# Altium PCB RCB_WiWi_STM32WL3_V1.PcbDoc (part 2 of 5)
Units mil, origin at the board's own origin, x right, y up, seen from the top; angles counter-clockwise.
Board outline 1250.1 x 2647.64 mil, 10 copper layers (L01-TOP, L02-GND, L03-SIG, L04-GND, L05-PWR, L06-PWR, L07-GND, L08-SIG, L09-GND, L10-BOT), stack 62.1 mil thick; 342 components, 203 nets, 969 pads, 708 vias.
Unrouted connection lines stored in the file: 108.
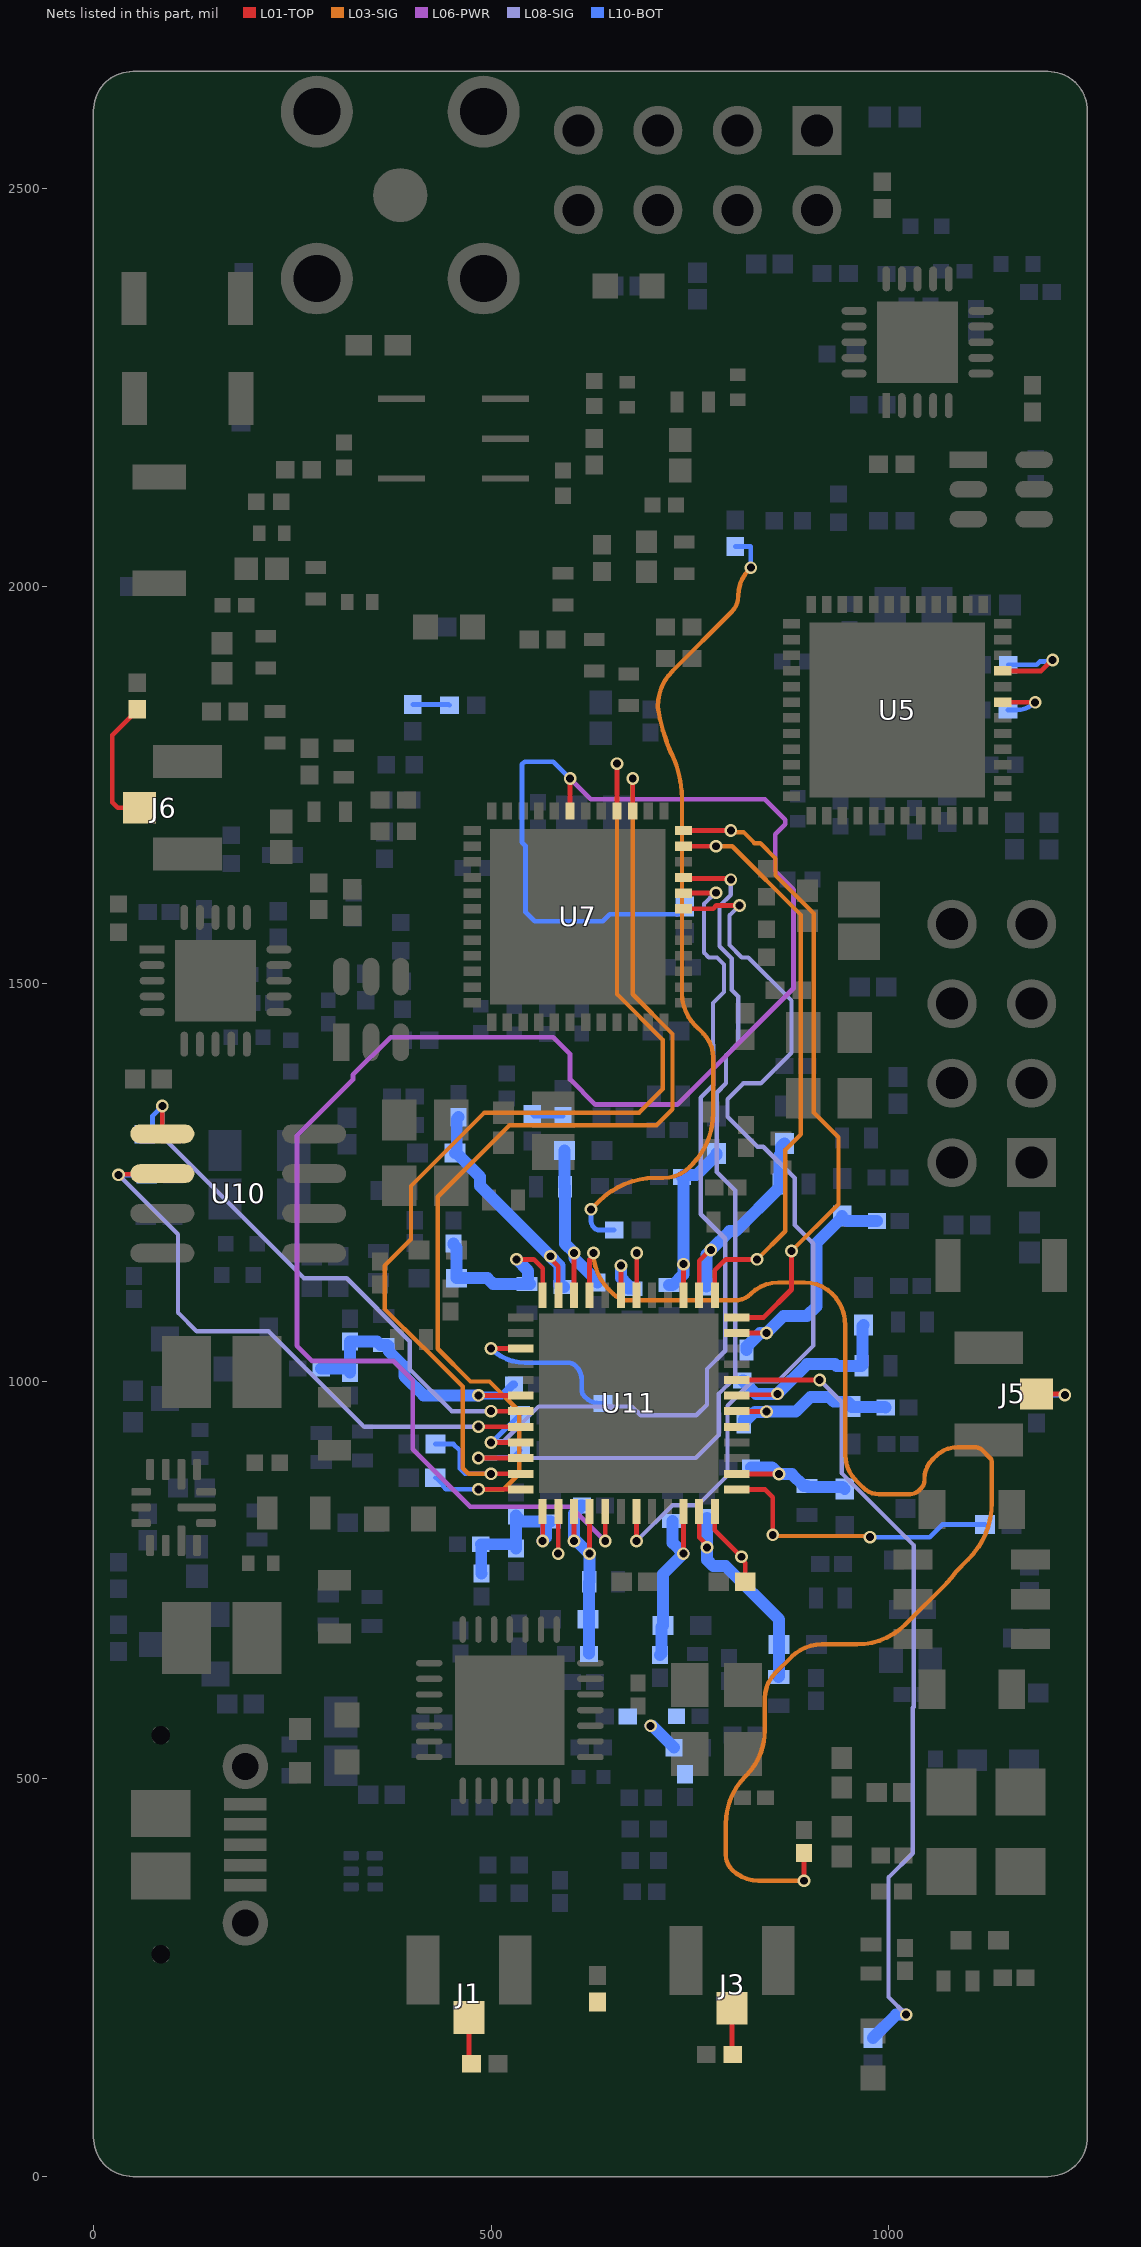
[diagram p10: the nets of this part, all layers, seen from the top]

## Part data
C1 C22 C24 C40 C41 C42 C44 C58 C62 C64 C68 C71 C73 C77 C80 C84 C87 C90 C92 C94 C97 C100 C102 C104 C107 C109 C112 C114 C131 C133 C147 C149: library part CMP-13271-000002-1, "CAP CER 10UF 10V X5R 0402", Capacitance=10uF, Manufacturer=Samsung, Manufacturer Part Number=CL05A106MP5NUNC, Temperature="-55°C to +85°C", Temperature Characteristic=X5R, Temperature Coefficient=15%, Temperature Range High=+85°C, Temperature Range Low=-55°C, Tolerance=20%, Voltage Rating=10V
C2 C13 C21 C23 C25 C26 C27 C31 C32 C33 C34 C47 C51 C55 C59 C60 C63 C65 C66 C67 C69 C70 C72 C74 C75 C76 C78 C79 C81 C82 C83 C85 C86 C88 C89 C91 C93 C95 C96 C98 C99 C101 C103 C106 C108 C110 C111 C113 C115 C118 C119 C121 C126 C127 C132 C134 C148 C150: library part CMP-2008-02519-2, "General Purpose Ceramic Capacitor, 0402, 100nF, 10%, X7R, 15%, 25V", Capacitance=100nF, Case Code (Imperial)=0402, Case Code (Metric)=1005, Dielectric=X7R, Max Operating Temperature=125°C, Min Operating Temperature=-55°C, Package Quantity=1, Tolerance=10%, Voltage=25V
C3 C8 C14 C19: library part CMP-2008-03915-1, Manufacturer=Murata, Part Number=GRM1555C1H101JA01D
C4 C15: library part CMP-2008-03815-2, "Multi-Layer Ceramic Capacitor 1.2pF C0G  ±0.05pF 0402 Paper T/R", Capacitance=1.2pF, Case Code (Imperial)=0402, Case Code (Metric)=1005, Dielectric=C0G, Max Operating Temperature=125°C, Min Operating Temperature=-55°C, Package Quantity=10000, Voltage=50V
C5 C6 C16 C17: library part CMP-06035-005630-1, "Multi-Layer Ceramic Capacitor 5pF C0G  ±0.05pF 0402 Paper T/R", Capacitance=5pF, Case Code (Imperial)=0402, Case Code (Metric)=1005, Dielectric=C0G, Max Operating Temperature=125°C, Min Operating Temperature=-55°C, Package Quantity=10000, Voltage Rating=50V
C7 C18: library part CMP-2008-03837-2, "Multi-Layer Ceramic Capacitor 2.2pF C0G  ±0.05pF 0402 Paper T/R", Capacitance=2.2pF, Case Code (Imperial)=0402, Case Code (Metric)=1005, Dielectric=C0G, Max Operating Temperature=125°C, Min Operating Temperature=-55°C, Package Quantity=10000, Voltage Rating=50V
C9 C10 C20 C28: library part CMP-2008-03904-2, "Multi-Layer Ceramic Capacitor 0.5pF C0G  ±0.1pF 0402 Paper T/R", Capacitance=0.5pF, Case Code (Imperial)=0402, Case Code (Metric)=1005, Dielectric=C0G, Max Operating Temperature=125°C, Min Operating Temperature=-55°C, Package Quantity=1, Temperature Coefficient=30ppm/°C, Voltage=50V
C11 C12 C29 C30 C35 C135 C137 C138 C139 C143 C151 C153 C154 C155 C159: library part CMP-1034-02068-3, "CAP CER 0.1UF 16V 5% X7R 0402", Capacitance="0.10 μF", Manufacturer=Kemet, Manufacturer Part Number=C0402C104J4RACTU, Package=C0402-BB, Temperature="-55°C to +125°C", Temperature Characteristic=X7R, Temperature Coefficient=15%, Temperature Range High=+125°C, Temperature Range Low=-55°C, Tolerance=0.05, Voltage Rating="16 V"
C36 C37 C140 C142 C156 C158: library part CMP-2000-05997-2, "CAP CER 4.7UF 10V X5R 0402", Capacitance=4.7uF, Case Code (Imperial)=0402, Case Code (Metric)=1005, Dielectric=X5R, Dielectric Material=Ceramic, Max Operating Temperature=85°C, Min Operating Temperature=-55°C, Package Quantity=10000, Tolerance=10%, Voltage Rating=10V
C38 C45 C48: library part CMP-2000-05441-1, "Chip Capacitor, 22 uF, +/- 20%, 10 V, -55 to 85 degC, 0603 (1608 Metric), RoHS, Tape and Reel", Capacitance=22µF, Manufacturer=TDK, Operating Temperature=-55degC~85degC, Package / Case=0603(1608Metric), Package Description="2-Pin Surface Mount Device, Body 1.6 x 0.8 mm", Package Reference=603, PCN Part Number=MLCCPartNumberChange30/Nov/2012, Ratings=-, Standard Package=1, Temperature Coefficient=X5R, Tolerance=±20%, Voltage - Rated=10V
C39 C43: library part CMP-08246-002674-1, "CAP CER 10PF 50V C0G 0402", Capacitance=10pF, Case Code (Imperial)=0402, Case Code (Metric)=1005, Dielectric=C0G, Dielectric Material=Ceramic, Max Operating Temperature=125°C, Min Operating Temperature=-55°C, Package Quantity=1, Temperature Coefficient=30ppm/°C, Voltage=50V
C46 C50 C117 C120 C125: library part CMP-2100-03592-2, "CAP CER 10000PF 50V X7R 0402", Capacitance="10 nF", Manufacturer=YAGEO, Manufacturer Part Number=CC0402KRX7R9BB103, Package=CC0402, Temperature="-55°C to +125°C", Temperature Characteristic=X7R, Temperature Coefficient=30ppm/°C, Temperature Range High=+125°C, Temperature Range Low=-55°C, Tolerance=0.1, Voltage Rating="50 V"
C49 C52 C122: library part CMP-13271-001468-1, "Cap Ceramic 4.7uF 16V X5R ±20% SMD 0402 +85°C Paper T/R", Capacitance=4.7uF, Case Code (Imperial)=0402, Case Code (Metric)=1005, Max Operating Temperature=85°C, Min Operating Temperature=-55°C, Tolerance=20%, Voltage Rating=16V
C53 C116 C123 C124: library part CMP-2008-04368-1, Manufacturer=Murata, Part Number=GRM1555C1H470JA01D
C54 C57: library part CMP-2000-05393-2, "Multilayer Ceramic Capacitors 100nF ±10% 50V X7R SMD 0402", Capacitance=100nF, Case Code (Imperial)=0402, Case Code (Metric)=1005, Dielectric=X7R, Dielectric Material=Ceramic, Max Operating Temperature=125°C, Min Operating Temperature=-55°C, Package Quantity=1, Tolerance=10%, Voltage=50V
C56: library part CMP-13271-004224-1, "Cap Ceramic 10uF 25V X5R ±20% Pad SMD 0603 +85°C T/R", Capacitance=10uF, Case Code (Imperial)=0603, Case Code (Metric)=1608, Dielectric=X5R, Max Operating Temperature=85°C, Min Operating Temperature=-55°C, Package Quantity=1, Tolerance=20%, Voltage Rating=25V
C61: library part CMP-2008-02907-1, Manufacturer="AVX Interconnect / Elco", Part Number=04025C222JAT2A
C105: library part CMP-2000-06226-4, "Multilayer Ceramic Capacitor 10uF 16V X5R 20% SMD 0603 T/R", Capacitance=10uF, Case Code (Imperial)=0603, Case Code (Metric)=1608, Dielectric=X5R, Max Operating Temperature=85°C, Min Operating Temperature=-55°C, Package Quantity=1, Tolerance=20%, Voltage Rating=16V
C128 C129 C144 C145: library part CMP-2008-03875-2, "Multi-Layer Ceramic Capacitor 6.8pF C0G  ±0.25pF 0402 Paper T/R", Capacitance=6.8pF, Case Code (Imperial)=0402, Case Code (Metric)=1005, Dielectric=C0G, Max Operating Temperature=125°C, Min Operating Temperature=-55°C, Package Quantity=1, Voltage=50V
C130 C146: library part CMP-14477-000104-2, "None", Capacitance=1uF, Case Code (Imperial)=0402, Case Code (Metric)=1005, Dielectric=X5R, Max Operating Temperature=85°C, Min Operating Temperature=-55°C, Package Quantity=1, Tolerance=10%, Voltage Rating=16V
C136 C152: library part CMP-1034-02089-3, "Chip Multilayer Ceramic Capacitors for General Purpose, 0402, 0.22uF, X7R, 15%, 10%, 16V", Capacitance=220nF, Case Code (Imperial)=0402, Case Code (Metric)=1005, Dielectric=X7R, Max Operating Temperature=125°C, Min Operating Temperature=-55°C, Package Quantity=1, Tolerance=10%, Voltage=16V
C141 C157: library part CMP-2008-00009-2, "CAP CER 20PF 50V C0G/NP0 0402", Capacitance="20 pF", Manufacturer=KEMET, Manufacturer Part Number=CBR04C200J5GAC, Package=CBR04C, Temperature="-55°C to +125°C", Temperature Characteristic=C0G, Temperature Coefficient=30ppm/°C, Temperature Range High=+125°C, Temperature Range Low=-55°C, Tolerance=0.05, Voltage Rating="50 V"
D1 D2 D3 D4 D8: library part CMP-22017-000005-2, "LED GREEN CLEAR CHIP SMD", Case Code (Imperial)=0603, Case Code (Metric)=1608, Color=Green, Forward Current=30mA, Forward Voltage=2.1V, Lens Color=Colorless, Max Operating Temperature=85°C, Min Operating Temperature=-55°C, Package Quantity=1, Power Dissipation=100mW, Reverse Voltage=5V, Test Current=10mA, Voltage=2V
D5: library part CMP-08607-000011-1, "TVS DIODE 14V 40V 0402", Breakdown Voltage=14V, Capacitance=0.25pF, Clamping Voltage=40V, Manufacturer="Littelfuse Inc.", Package=PESD0402, Temperature="-55°C to +125°C", Temperature Range High=+125°C, Temperature Range Low=-55°C
FB1 FB3 FB4: library part CMP-0686-00581-3, "Chip Ferrite Bead, 0603, 600Ω @ 100MHz, 0.15Ω, 25%, 1.3A", Case Code (Imperial)=0603, Case Code (Metric)=1608, Current Rating=1.3A, DC Resistance (DCR)=150mR, Inductor Type="FERRITE BEAD", Max Operating Temperature=125°C, Min Operating Temperature=-55°C, Package Quantity=1, Test Frequency=100MHz, Tolerance=25%
FB2: library part CMP-0220-00171-2, "FERRITE BEAD 300 OHM 0603 1LN", Case Code (Imperial)=0603, Case Code (Metric)=1608, Case/Package=SMD/SMT, Current Rating=2A, DC Resistance (DCR)=150mR, Inductance=18nH, Max Operating Temperature=125°C, Min Operating Temperature=-55°C, Package Quantity=1, Test Frequency=100MHz, Tolerance=25%
J1 J3 J5 J6: library part CMP-2000-05152-3, "CONN U.FL RCPT STR 50 OHM SMD", Dielectric Material=Polymer, Frequency=6GHz, Housing Color=Beige, Insulation Resistance=500MR, Max Operating Temperature=90°C, Min Operating Temperature=-40°C, Package Quantity=2500
J2: library part CMP-2000-05827-1, "Micro-USB B Receptacle, Right Angle, Bottom Mount, Surface Mount, with Solder Tabs, -30 to 85 degC, 5-Pin USB, RoHS, Tape and Reel", Manufacturer=Molex, Package Description="5-Leads USB, Micro B, Body 7.5 x 5 mm, Pitch 0.65 mm", Package Reference=MICRO-B, Package Version="Rev. F, 12/2012", Standard Package=1, Voltage - Max=30V
J4: library part CMP-02754-000007-1, "CONN SMA JACK STR 50 OHM SMD", Case/Package=SMA, Dielectric Material=PTFE, Housing Color=Gold, Max Frequency=20GHz, Max Operating Temperature=125°C, Min Operating Temperature=-65°C, Voltage Rating=335V
J7 J8: library part CMP-02766-000066-1, "CONN HEADER VERT 8POS 2.54MM", Current Rating=6.3A, Manufacturer=Samtec, Temperature="-55°C to +125°C", Temperature Range High=+125°C, Temperature Range Low=-55°C, Voltage Rating=550V
L1 L20 L21 L25: library part CMP-06042-001817-1, "Wire Wound RF Inductor 12nH ±2% 1240mA 0.093Ω 0402 (1005)", Case Code (Imperial)=0402, Case Code (Metric)=1005, Current Rating=1.24A, DC Resistance (DCR)=93mR, Inductance=12nH, Max Operating Temperature=125°C, Min Operating Temperature=-55°C, Package Quantity=10000, Resistor Type=Wirewound, Self Resonant Frequency=5.2GHz, Test Frequency=100MHz, Tolerance=2%
L2 L3 L4 L5 L6 L7 L8 L11 L12 L13 L14 L15 L16 L26 L29: library part CMP-0220-00137-1, "SMD EMI Suppression Ferrite Bead WE-CBF, Z = 220 Ohm"
L9 L10: library part CMP-06042-015149-1, "Shielded Wirewound Inductor 0.47uH 20% 4000mA 0.027Ω 1008 (2520)"
L17 L22: library part CMP-06042-000856-1, "Wire Wound RF Inductor 7.5nH ±2% 1700mA 0.05Ω 0402 (1005)", Case Code (Imperial)=1005, Case Code (Metric)=0402, Current Rating=1.7A, DC Resistance (DCR)=50mR, Inductance=7.5nH, Max Operating Temperature=125°C, Min Operating Temperature=-55°C, Package Quantity=10000, Resistor Type=Wirewound, Self Resonant Frequency=7GHz, Test Frequency=100MHz, Tolerance=2%
L18 L19 L23 L24: library part CMP-06042-008137-1, "Wire Wound RF Inductor 13nH ±2% 1240mA 0.093Ω 0402 (1005)", Case Code (Imperial)=0402, Case Code (Metric)=1005, Current Rating=1.24A, DC Resistance (DCR)=93mR, Inductance=13nH, Max Operating Temperature=125°C, Min Operating Temperature=-55°C, Package Quantity=10000, Resistor Type=Wirewound, Self Resonant Frequency=5.2GHz, Test Frequency=100MHz, Tolerance=2%
L27 L30: library part CMP-06042-014493-1, "Multilayer Type Inductor for Power Lines, 0805 (2012), 10μH, 20%, 0.39Ω, 100mA", Case Code (Imperial)=0805, Case Code (Metric)=2012, Current Rating=100mA, DC Resistance (DCR)=300mR, Inductance=10uH, Inductance Tolerance=20%, Max Operating Temperature=125°C, Min Operating Temperature=-40°C, Package Quantity=3000, Self Resonant Frequency=15MHz, Test Frequency=1MHz
L28 L31: library part CMP-06042-015241-1, "Multilayer type RF Inductor 100nH ±5% 1.25Ω 200mA 0402", Case Code (Imperial)=0402, Case Code (Metric)=1005, Current Rating=150mA, DC Resistance (DCR)=1.25R, Inductance=100nH, Max Operating Temperature=125°C, Min Operating Temperature=-55°C, Package Quantity=10000, Self Resonant Frequency=600MHz, Test Frequency=100MHz, Tolerance=5%
Q1 Q2: library part CMP-1058-00766-2, "MOSFET N-CH 60V 320MA SOT-23", Case/Package=SOT-23-3, Continuous Drain Current (ID)=320mA, Drain to Source Breakdown Voltage=60V, Drain to Source Resistance=1.6R, Gate to Source Voltage (Vgs)=20V, Input Capacitance=24.5pF, Max Operating Temperature=150°C, Max Power Dissipation=420mW, Min Operating Temperature=-55°C, Package Quantity=1, Power Dissipation=300mW, Threshold Voltage=2.3V
R1 R2 R4 R5 R6 R9 R33 R34 R35 R36 R37 R38 R39 R40 R41 R42 R44 R57 R59 R61 R67 R68 R76 R79 R82 R83 R86 R87 R97 R103 R104 R107 R108: library part CMP-2002-06457-1, Manufacturer=Panasonic, Part Number=ERJ-U020R00X
R3 R8: library part CMP-2002-06458-1, Manufacturer=Panasonic, Part Number=ERJ-U02F1000X
R7 R26: library part CMP-2002-04448-1, Manufacturer="KOA Speer", Part Number=RK73H1ETTP49R9F
R10: library part CMP-2002-01027-1, Manufacturer=Panasonic, Part Number=ERJ-2RKF6490X
R11 R12 R13 R14 R62 R63 R64 R65: library part CMP-2002-08434-1, Manufacturer="Vishay Dale", Part Number=CRCW040227R0FKED
R15: library part CMP-2002-05709-1, Manufacturer="TE Connectivity / AMP", Part Number=CRG0402F20K
R16 R17 R71 R72 R93: library part CMP-2002-05853-1, Manufacturer=Panasonic, Part Number=ERA-2AED331X
R18 R19 R20 R21 R22 R23 R24 R25 R27 R28 R29 R30 R31 R32 R45 R46 R49 R50 R69 R89 R90 R95 R96 R110 R111: library part CMP-2002-05217-1, Manufacturer=Bourns, Part Number=CR0402-FX-4701GLF
R47 R51 R52: library part CMP-2002-04569-1, Manufacturer="KOA Speer", Part Number=RK73Z1ETTP
R48: library part CMP-2002-08277-1, Manufacturer="Vishay Dale", Part Number=CRCW04021K00FKTD
R53 R54 R56 R73 R74 R75 R77 R78 R91 R92 R100 R101 R112 R113: library part CMP-2002-04694-1, Manufacturer=Bourns, Part Number=CR0402-FX-1002GLF
R55 R66: library part CMP-2002-07353-1, Manufacturer="Yageo / Phycomp", Part Number=RC0402FR-0710KL
R58: library part CMP-1011-00697-1, "45K3 0.063W 1% 0402 (1005 Metric)  SMD", Case-EIA=0402, Case-Metric=1005, Power="0.063 W", Tolerance="1 %"
R60 R70: library part CMP-2002-00694-4, "RES SMD 15K OHM 1% 1/10W 0402", Manufacturer=Panasonic, Manufacturer Part Number=ERJ-2RKF1502X, Package=ERJ2R, Power Rating=0.1W, Resistance=15kΩ, Temperature="-55°C to +155°C", Temperature Coefficient=100ppm/°C, Temperature Range High=+155°C, Temperature Range Low=-55°C, Tolerance=1%, Voltage Rating=50V
R81 R85 R102 R106: library part CMP-2002-00202-1, Manufacturer="Vishay Dale", Part Number=CRCW040271R5FKED
R84 R88 R105 R109: library part CMP-2002-08233-1, Manufacturer="Vishay Dale", Part Number=CRCW0402165RFKED
R98: library part CMP-2002-00253-3, "Chip Resistor, 8.06 KOhm, +/- 1%, 63 mW, -55 to 155 degC, 0402 (1005 Metric), RoHS, Tape and Reel", Case Code (Imperial)=0402, Case Code (Metric)=1005, Manufacturer="Basic Passives", Max Operating Temperature="155 degC", Min Operating Temperature="-55 degC", Package Quantity=10000, PartNumber=CRCW04028K06FKED, Power Rating="63 mW", Resistance="8.06 KOhm", Tolerance=1%, Voltage Rating="50 V"
SW1 SW2 SW3 SW4: library part CMP-2100-03586-2, "SWITCH TACTILE SPST-NO 0.05A 12V", Contact Current Rating=50mA, Contact Resistance=100mR, Insulation Resistance=100MR, Max Operating Temperature=70°C, Max Voltage Rating (DC)=12V, Min Operating Temperature=-25°C, Operating Force=1.5N, Package Quantity=1, Ratings="Dust Proof"
U1: "No Description Available", Mfr_Name="Mini Circuits"
U2: library part CMP-0967-00085-1, "HX2VL(TM) Very Low Power USB 2.0 Hub Controller, 2 Hub Ports, 0 to 70 degC, 28-Pin QFN (LTX28), Bulk", Manufacturer=Cypress, Max. Operating Temp. (degreesC)=70, Max. Operating Voltage (V)=5.25, Min. Operating Temp. (degreesC)=0, Min. Operating Voltage (V)=3.15
U3 U4: library part CMP-0248-00001-3, "IC USB SERIAL FULL UART 20QFN", Case/Package=QFN, Max Operating Temperature=85°C, Max Supply Voltage=5.5V, Min Operating Temperature=-40°C, Min Supply Voltage=2.97V, Operating Supply Current=8mA, Package Quantity=5000
U5 U7: "No Description Available", Mfr_Name=STMicroelectronics
U6 U8: library part CMP-0859-00203-4, "IC SWITCH SPDT SOT23-6", Case/Package=SOT-23, High Level Output Current=128mA, Max Operating Temperature=125°C, Max Supply Current=10uA, Max Supply Voltage=5.5V, Min Operating Temperature=-40°C, Min Supply Voltage=1.65V, On-State Resistance=15R, Operating Supply Current=1uA, Package Quantity=3000
U10: library part CMP-0159-01024-1, "1024K bits I2C™ Serial EEPROM, 2.5 to 5.5 V, 400 kHz, -40 to 85 degC, 8-pin SOIC (SN8), Tube", Manufacturer=Microchip
U11: "No Description Available", Mfr_Name="Renesas Electronics"
U13: library part CMP-0326-00032-3, "Low-Capacitance + / - 15 kV ESD-Protection Array for High-Speed Data Interfaces, 3 Channels, -40 to +85 degC, 6-pin SON (DRY), Green (RoHS & no Sb/Br)", Breakdown Voltage(Min)(V)=11, IO Capacitance(Typ)(pF)=1.5, IO Leakage Current(nA)=Jan-00, Manufacturer="Texas Instruments"
U14: library part CMP-04918-000654-1, "Adjustable-Frequency Dual Step-Down Converter, 2.7-6V VIN, 0.6-5.5V 2A VOUT, VQFN-HR14"
Y1: library part CMP-25159-259584-1, "MEMS OSC TCXO 40.0000MHZ LVCMOS", Case/Package=SMD/SMT, Frequency=40MHz, Frequency Stability=5ppm, Max Operating Temperature=70°C, Max Supply Current=33mA, Min Operating Temperature=-20°C
Y2: library part CMP-2000-05039-3, "Crystal 12MHz ±20ppm (Tol) ±30ppm (Stability) 18pF FUND 120Ω 4-Pin SMD T/R", Case/Package=CSMD, ESR (Equivalent Series Resistance)=120R, Frequency=12MHz, Frequency Stability=30ppm, Frequency Tolerance=20ppm, Load Capacitance=18pF, Max Operating Temperature=85°C, Min Operating Temperature=-40°C, Operating Frequency="12 MHz", Package Quantity=1000
Y3 Y6: library part CMP-200220-000005-1, "CRYSTAL 32.768KHZ 7PF SMD", Frequency=32.768kHz, Load Capacitance=12.5pF, Manufacturer="NDK America", Package=NX2012SA, Temperature="-40°C to +85°C", Temperature Range High=+85°C, Temperature Range Low=-40°C, Tolerance=20ppm
Y4: library part CMP-OSC-00029-2, "OSC, MEMS, STRATUM 3E, 10.000MHZ, 10PPB STAB, LVCMOS, 3.3V, O/P EN, 7.0X5.0X2.2MM, CQFN-10", Case/Package="10 Lead QFN", Frequency="10 MHz", Frequency Stability="±10 ppb", Manufacturer=SiTime, Manufacturer Part Number=SiT5501AI-WU033JH-10.000000, Max Operating Temperature=70°C, Min Operating Temperature=-20°C, Voltage - Supply="3.3 V"
Y5 Y7: library part CMP-27762-000273-1, "XTAL Oscillator 48MHz ±50ppm CMOS 3.3V 4-SMD 3.2mm x 2.5mm", Case/Package=SMD/SMT, Frequency=48MHz, Frequency Stability=50ppm, Load Capacitance=15pF, Max Operating Temperature=85°C, Max Supply Current=19mA, Max Supply Voltage=3.465V, Min Operating Temperature=-40°C, Min Supply Voltage=3.135V, Operating Frequency="48 MHz", Operating Supply Voltage=3.3V, Package Quantity=1000

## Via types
v1: diameter 16, hole 10, L01-TOP to L10-BOT, tented both sides, 699 vias
v2: diameter 16, hole 10, L01-TOP to L10-BOT, 9 vias

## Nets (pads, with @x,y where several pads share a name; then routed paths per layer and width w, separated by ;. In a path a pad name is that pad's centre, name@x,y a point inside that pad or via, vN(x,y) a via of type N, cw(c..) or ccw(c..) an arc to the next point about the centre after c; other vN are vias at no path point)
DPLL_CLKIN0_P: R34.1 U5.9 | length 126.6
  L01-TOP w6: U5.9@1143.7,1893.71 1191.82,1893.71 1205.51,1907.39 v1(1206.42,1907.39)
  L10-BOT w6: R34.1@1150.59,1901.57 1186.42,1901.57 1190.33,1905.48 1204.51,1905.48 v1(1206.42,1907.39)
DPLL_CLKIN1_N: J1.1 R44.1 | length 59.3
  L01-TOP w6: J1.1@472.44,199.8 472.44,144.69 R44.1@475.39,141.73
DPLL_CLKIN1_P: R36.1 R76.2 | length 39.7
  L10-BOT w6: R36.1@551.85,1336.02 554.21,1333.66 R76.2@590.55,1333.66
DPLL_CLKOUT8_N: R33.2 R107.1 | length 46.7
  L10-BOT w6: R107.1@401.57,1851.38 446.85,1851.38 R33.2@447.83,1850.39
DPLL_CLKOUT8_P: R39.2 R86.1 | length 1058.1
  L03-SIG w5.5: v1(625.72,1216.54) 635.8,1226.62 cw(c706.51,1155.91) 706.51,1255.91 716.54,1255.91 ccw(c716.54,1303.43) 750.14,1269.82 751.97,1271.65 ccw(c685.43,1338.19) 779.53,1338.19 779.53,1407.61 ccw(c737.27,1407.61) 767.15,1437.49 757.03,1447.61 cw(c797.78,1488.35) 740.16,1488.35 740.16,1731.46 740.16,1731.54 ccw(c602.01,1731.51) 728.34,1787.42 ccw(c723.33,1785.14) 727.92,1788.18 726.66,1790.08 cw(c934.17,1881.98) 709.69,1848.6 cw(c773.52,1848.6) 728.38,1893.74 802.67,1968.03 ccw(c782.51,1988.19) 811.02,1988.19 cw(c858.55,1988.19) 824.94,2021.79 v1(826.77,2023.62)
  L10-BOT w6: v1(625.72,1216.54) 625.72,1203.05 ccw(c640.06,1203.05) 629.92,1192.91 ccw(c635.82,1198.81) 635.82,1190.47 R39.2@655.07,1190.47 ; R86.1@807.09,2050.2 826.77,2050.2 v1(826.77,2023.62)
DPLL_CLKOUT9_N: R35.2
DPLL_CLKOUT9_P: J5.1 R40.2 | length 72.4
  L01-TOP w6: J5.1@1186.02,984.25 1220.43,984.25 v1(1221.74,982.94)
  L10-BOT w6: R40.2@1186.02,981.3 cw(c1190,977.33) 1190,982.94 v1(1221.74,982.94)
DPLL_CLKOUT10_N: R37.2 U11.3 | length 216.7
  L01-TOP w6: v1(500,1041.34) U11.3@537.23,1041.34
  L10-BOT w6: v1(500,1041.34) ccw(c542.77,1084.11) 542.77,1023.62 596.79,1023.62 cw(c596.79,1010.18) 606.3,1019.68 607.21,1018.77 cw(c590.41,1001.97) 614.17,1001.97 614.17,989.82 ccw(c627.61,989.82) 618.11,980.32 ccw(c637.12,999.33) 637.12,972.44 R37.2@640.75,972.44
DPLL_CLKOUT10_P: R41.2 U5.7 | length 77.8
  L01-TOP w6: U5.7@1143.7,1854.33 1184.36,1854.33 v1(1184.46,1854.23)
  L10-BOT w6: R41.2@1150.11,1844.48 1160.91,1844.48 ccw(c1160.91,1877.78) v1(1184.46,1854.23)
DPLL_CLKOUT11_N: J6.1 R38.2 | length 167.5
  L01-TOP w6: R38.2@55.12,1845.47 55.12,1844.49 23.62,1812.99 23.62,1728.35 30.51,1721.46 J6.1@58.07,1721.46
DPLL_CLKOUT11_P: J3.1 R42.2 | length 58.5
  L01-TOP w6: J3.1@803.15,211.61 803.15,154.53 R42.2@804.13,153.54
DPLL_CREG_XTAL: C58.1 U11.43 | length 74.6
  L01-TOP w6: U11.43@663.39,1108.44 v1(663.39,1145.67)
  L10-BOT w15: v1(663.39,1145.67) 663.58,1145.48 663.58,1130.22 671.38,1122.42 671.38,1117.99 672.74,1116.63 C58.1@677.17,1116.63
DPLL_CS: R46.1 U7.8 U11.9 | length 1131.5
  L01-TOP w6: v1(499.89,923.23) U11.9@537.12,923.23 ; U7.8@742.13,1614.17 742.38,1614.43 782.62,1614.43 v1(782.88,1614.69)
  L08-SIG w5.5: v1(499.89,923.23) 501.49,924.82 516.14,924.82 559.82,968.5 677.17,968.5 688.28,957.39 758.2,957.39 771.65,970.84 771.65,1015.65 794.61,1038.61 794.61,1179.45 763.78,1210.28 763.78,1357.04 779.53,1372.79 779.53,1423.6 779.25,1423.88 779.25,1475.94 793.09,1489.78 793.09,1524.5 784.27,1533.31 773.95,1533.31 767.83,1539.43 767.83,1600.62 781.9,1614.69 v1(782.88,1614.69)
  L10-BOT w6: v1(499.89,923.23) 501.14,923.23 535.51,957.6 R46.1@536.5,957.6
DPLL_EEPROM_SCL: R19.2 U10.6 U11.8 | length 786
  L01-TOP w6: v1(31.5,1259.84) 32.28,1260.63 85.83,1260.63 U10.6@86.61,1261.42 ; v1(484.17,943.13) 484.28,943.02 U11.8@537.12,943.02
  L08-SIG w5.5: v1(31.5,1259.84) 106.3,1185.04 106.3,1086.61 129.92,1062.99 220.47,1062.99 340.34,943.13 v1(484.17,943.13)
  L10-BOT w6: v1(31.5,1259.84) 66.07,1259.84 R19.2@66.86,1260.63
DPLL_EEPROM_SDA: R18.2 U10.5 U11.7 | length 732.9
  L01-TOP w6: U10.5@86.61,1311.42 v1(86.61,1346.46) ; v1(500,962.6) U11.7@537.23,962.6
  L08-SIG w5.5: v1(86.61,1346.46) 86.61,1308.03 264.72,1129.92 318.43,1129.92 397.64,1050.72 397.64,1015.75 450.79,962.6 v1(500,962.6)
  L10-BOT w6: R18.2@64.53,1310.97 65.52,1310.97 74.33,1319.78 74.33,1334.17 v1(86.61,1346.46)
DPLL_FILTER: C59.1 C60.1 R47.2 R48.2 U11.14 | length 94.1
  L01-TOP w6: v1(584.43,783.38) 584.54,783.49 584.54,836.33 U11.14@584.65,836.44
  L10-BOT w15: v1(700.79,566.93) 700.98,566.74 702.95,566.74 R48.2@730.31,539.37
DPLL_GPIO0: U11.42 | length 53
  L01-TOP w6: U11.42@683.18,1108.55 683.18,1161.39 v1(683.29,1161.5)
DPLL_GPIO1: R71.1 U11.32 | length 1027.7
  L01-TOP w6: U11.32@809.34,1001.86 809.44,1001.97 v1(913.39,1001.97)
  L08-SIG w5.5: v1(913.39,1001.97) 940.94,974.41 940.94,884.73 1031.5,794.18 1031.5,590.55 1030.32,589.38 1030.32,406.57 1000,376.25 1000,225.73 v1(1022.2,203.53)
  L10-BOT w15: R71.1@980.31,174.21 1009.64,203.53 v1(1022.2,203.53)
DPLL_GPIO2: U11.29
DPLL_GPIO3: U7.7 U11.19 | length 1176.2
  L01-TOP w6: v1(683.07,799.21) U11.19@683.07,836.44 ; U7.7@742.13,1594.48 779.25,1594.48 783.49,1598.73 v1(812.49,1598.73)
  L08-SIG w5.5: v1(683.07,799.21) 727.94,844.08 759.8,844.08 797.46,881.74 797.46,969.57 827.9,1000.02 860.26,1000.02 905.51,1045.28 905.51,1173.23 881.89,1196.85 881.89,1255.91 842.52,1295.28 835.22,1295.28 797.46,1333.04 797.46,1354.92 817.47,1374.93 839.5,1374.93 877.95,1413.39 877.95,1479 823.64,1533.31 815.48,1533.31 799.91,1548.88 799.91,1586.15 v1(812.49,1598.73)
DPLL_GPIO4: U7.11 U11.37 | length 729.7
  L01-TOP w6: U7.11@742.13,1673.24 782.79,1673.24 v1(782.88,1673.15) ; U11.37@781.5,1108.44 781.5,1139.76 795.28,1153.54 v1(834.65,1153.54)
  L03-SIG w5.5: v1(782.88,1673.15) 803.34,1673.15 889.76,1586.72 889.76,1310.96 870.08,1291.27 870.08,1188.98 v1(834.65,1153.54)
DPLL_GPIO5: U7.12 U11.36 | length 812.9
  L01-TOP w6: U7.12@742.13,1692.93 v1(801.64,1692.93) ; U11.36@809.34,1080.6 842.9,1080.6 877.95,1115.65 v1(877.95,1163.97)
  L03-SIG w5.5: v1(801.64,1692.93) 803.65,1690.92 817.49,1690.92 831.25,1677.17 838.58,1677.17 857.83,1657.92 857.83,1636.75 905.85,1588.73 905.85,1338.24 937.01,1307.09 937.01,1223.03 v1(877.95,1163.97)
DPLL_GPIO8: R23.2 U11.25 | length 371.2
  L01-TOP w6: U11.25@809.23,864.17 844.49,864.17 854.33,854.33 v1(854.33,807.09)
  L03-SIG w5.5: v1(854.33,807.09) 855.81,805.61 975.12,805.61 v1(976.6,804.13)
  L10-BOT w6: v1(976.6,804.13) 1051.77,804.13 1067.66,820.02 R23.2@1121.26,820.02
DPLL_GPIO9: R22.2 U11.24 | length 104.2
  L01-TOP w6: U11.24@781.39,836.33 781.39,813.1 v1(814.96,779.53) 814.96,776.82 819.88,771.9 R22.2@819.88,748.03
DPLL_OSCI: C21.2 U11.45 | length 1684.7
  L01-TOP w6: U11.45@624.02,1108.44 624.02,1153.79 629.02,1158.79 v1(629.02,1161.5) ; v1(893.63,372.04) 893.7,372.1 C21.2@893.7,406.87
  L03-SIG w5.5: v1(629.02,1161.5) ccw(c693.56,1161.5) 647.92,1115.86 653.54,1110.24 ccw(c673.58,1130.27) 673.58,1101.94 806.74,1101.94 ccw(c806.74,1130.27) 826.77,1110.24 cw(c861.06,1075.94) 861.06,1124.44 894.84,1124.44 cw(c894.84,1075.94) 929.13,1110.24 cw(c889.41,1070.51) 945.59,1070.51 945.59,908.14 ccw(c991.66,908.14) 959.08,875.56 968.5,866.14 ccw(c987.51,885.15) 987.51,858.27 1027.39,858.27 ccw(c1027.39,873.26) 1037.99,862.66 1041.22,865.88 ccw(c1031.51,875.59) 1045.24,875.59 1045.24,877.73 cw(c1078.97,877.73) 1055.12,901.57 1059.73,906.19 cw(c1086.61,879.3) 1086.61,917.32 1108.61,917.32 cw(c1108.61,903.88) 1118.11,913.39 1127.35,904.15 cw(c1121.13,897.93) 1129.92,897.93 1129.92,847.3 cw(c1029.92,847.3) 1100.63,776.59 1084.78,760.73 cw(c1012.88,807.09) 1073.37,746.6 1021.12,694.35 cw(c960.63,754.83) 960.63,669.29 915.97,669.29 ccw(c915.97,615.52) 877.95,653.54 857.57,633.16 ccw(c889.14,601.58) 844.49,601.58 844.49,561.84 cw(c762.61,561.84) 820.51,503.94 ccw(c881.42,443.03) 795.28,443.03 795.28,404.84 ccw(c822.16,404.84) 803.15,385.83 ccw(c836.44,419.12) 836.44,372.04 v1(893.63,372.04)
DPLL_RST_N: R31.1 U7.19 U11.17 | length 2667
  L01-TOP w6: U7.19@599.41,1717.51 599.41,1758.17 v1(599.51,1758.26) ; v1(643.7,799.21) U11.17@643.7,836.44
  L06-PWR w6: v1(599.51,1758.26) 625.55,1732.22 844.46,1732.22 870.08,1706.6 870.08,1700.79 857.47,1688.18 857.47,1641.53 880.45,1618.54 880.45,1494.63 734.05,1348.22 631.12,1348.22 599.4,1379.95 599.4,1411.85 578.18,1433.07 373.86,1433.07 326.32,1385.53 326.32,1379.49 255.91,1309.07 255.91,1044.93 275.18,1025.66 377.54,1025.66 401.57,1001.62 401.57,914.69 473.74,842.52 600.39,842.52 v1(643.7,799.21)
  L10-BOT w6: v1(599.51,1758.26) 578.24,1779.53 542.38,1779.53 538.86,1776.01 538.86,1678.37 543.31,1673.93 543.31,1590.55 555.12,1578.74 640.52,1578.74 649.41,1587.63 734.82,1587.63 743.63,1596.44 R31.1@743.63,1597.43
DPLL_SCLK: R49.1 U7.15 U11.12 | length 1396.9
  L01-TOP w6: v1(484.17,864.39) 484.28,864.28 U11.12@537.12,864.28 ; U7.15@678.15,1717.51 678.15,1758.17 v1(678.25,1758.26)
  L03-SIG w5.5: v1(484.17,864.39) 516.12,864.39 535.56,883.83 535.56,962.6 498.16,1000 474.17,1000 433.07,1041.1 433.07,1232.28 523.14,1322.36 708.18,1322.36 728.35,1342.52 728.35,1437.01 678.25,1487.11 v1(678.25,1758.26)
  L10-BOT w6: R49.1@430.04,878.76 431.02,878.76 439.84,869.95 439.84,867.9 443.35,864.39 v1(484.17,864.39)
DPLL_SDI: R45.1 U7.9 U11.10 | length 1228.2
  L01-TOP w6: v1(484.06,903.76) 484.17,903.65 U11.10@537.01,903.65 ; U7.9@742.13,1633.86 743.5,1632.49 800.33,1632.49 v1(801.7,1631.11)
  L08-SIG w5.5: v1(484.06,903.76) 757.66,903.76 786.23,932.33 786.23,984.37 807.09,1005.23 807.09,1240.16 783.83,1263.41 783.83,1363.23 795.53,1374.93 795.53,1410.06 811.02,1425.55 811.02,1484.25 802.89,1492.39 802.89,1532.05 787.4,1547.53 787.4,1597.92 801.7,1612.22 v1(801.7,1631.11)
  L10-BOT w6: v1(484.06,903.76) 507.28,903.76 508.1,904.57 527.68,904.57 R45.1@536.5,913.39
DPLL_SDIO: R50.1 U7.16 U11.11 | length 1444.2
  L01-TOP w6: v1(500,883.86) U11.11@537.23,883.86 ; U7.16@658.46,1717.51 v1(658.46,1777.03)
  L03-SIG w5.5: v1(500,883.86) 471.4,883.86 464.57,890.69 464.57,993.61 415.78,1042.39 414.93,1042.39 366.14,1091.18 366.14,1145.67 399.44,1178.97 399.44,1245.9 491.73,1338.19 686.44,1338.19 716.08,1367.82 716.08,1429.59 658.46,1487.21 v1(658.46,1777.03)
  L10-BOT w6: R50.1@430.12,921.26 452.76,921.26 460.63,913.39 460.63,890.57 467.35,883.86 v1(500,883.86)
DPLL_VDD_CLK: C94.1 C95.1 L11.2 U11.48 | length 251.2
  L01-TOP w6: v1(532.13,1153.54) 553.9,1153.54 565.07,1142.37 U11.48@565.07,1108.55
  L10-BOT w15: C95.1@452.61,1173.67 452.61,1172.31 456.69,1168.23 L11.2@456.69,1129.92 495.34,1129.92 502.46,1122.8 549.34,1122.8 547.87,1122.8 546.51,1124.16 546.51,1139.16 v1(532.13,1153.54)
DPLL_VDD_DCO_Q8: C62.1 C63.1 L4.2 U11.38 | length 288.5
  L01-TOP w6: U11.38@761.92,1108.55 761.92,1151.65 775.62,1165.35 v1(776.5,1165.35)
  L10-BOT w15: C63.1@771.1,1119.28 771.1,1159.69 776.5,1165.08 v1(776.5,1165.35) 800.12,1188.98 807.85,1188.98 862.86,1243.99 C62.1@862.86,1248.42 862.86,1284.2 864.73,1286.07 864.73,1295.04 L4.2@869.04,1299.35
DPLL_VDD_DCO_Q9: C77.1 C78.1 L5.2 U11.31 | length 278.2
  L01-TOP w6: U11.31@809.23,982.28 810.32,983.38 859.23,983.38 v1(860.33,984.47)
  L10-BOT w15: C78.1@816.12,1001.39 817.47,1001.39 820.05,998.81 820.05,997.45 833.03,984.47 v1(860.33,984.47) 897.63,1021.77 932.6,1021.77 934.68,1019.68 C77.1@966.04,1019.68 967.27,1020.92 967.27,1069.64 L5.2@968.5,1070.87
DPLL_VDD_DCO_Q10: C87.1 C88.1 L7.2 U11.30 | length 236.1
  L01-TOP w6: U11.30@811.41,962.6 811.72,962.29 846.15,962.29 v1(846.46,961.98)
  L10-BOT w15: C87.1@817.93,947.91 817.93,952.34 819.29,953.7 823.72,953.7 831.81,961.79 846.27,961.79 v1(846.46,961.98) 883.24,961.98 901.57,980.32 925.2,980.32 931.05,974.46 948.44,974.46 952.76,970.15 L7.2@952.76,968.67 953.45,967.98 995.71,967.98 C88.1@996.4,967.29
DPLL_VDD_DCO_Q11: C97.1 C98.1 L12.2 U11.23 | length 295.7
  L01-TOP w6: U11.23@761.81,836.44 761.81,803.89 771.65,794.04 v1(771.65,791.34)
  L10-BOT w15: C98.1@771.65,828.13 v1(771.65,791.34) 771.84,791.15 771.84,775.4 779.53,767.72 795.28,767.72 862.2,700.79 L12.2@862.2,669.29 862.02,669.11 862.02,628.72 C97.1@861.84,628.53
DPLL_VDD_DIG: C64.1 C65.1 C66.1 C67.1 R51.2 U11.6 | length 381.7
  L01-TOP w6: v1(484.17,982.5) 484.28,982.39 U11.6@537.12,982.39
  L10-BOT w10: v1(484.17,982.5) 484.28,982.6 514.1,982.6 527.56,996.06 C65.1@528.92,996.06
  L10-BOT w15: R51.2@286.42,1016.31 318.9,1016.31 322.83,1012.37 C67.1@322.83,1011.01 322.88,1011.06 C66.1@322.92,1050.13 C66.1@322.92,1050.13 356.57,1050.13 360.67,1046.03 369.53,1046.03 370.89,1044.67 370.89,1038.67 391.01,1018.56 391.01,1006.63 415.14,982.5 v1(484.17,982.5)
DPLL_VDD_GPIO: C80.1 C81.1 C82.1 C83.1 R52.2 U11.13 | length 235
  L01-TOP w6: v1(564.96,799.21) U11.13@564.96,836.44
  L10-BOT w15: C83.1@488.19,758.49 487.7,758.98 487.7,794.78 R52.2@487.2,795.28 527.56,795.28 C82.1@531.5,791.34 ; C82.1@531.5,789.98 C82.1@531.5,791.34 ; C81.1@531.5,831.68 C81.1@531.5,830.33 ; v1(564.96,799.21) 564.96,799.48 569.02,803.54 569.02,822.63 C80.1@570.37,823.99 ; C80.1@574.8,823.99 C80.1@570.37,823.99 ; C82.1@531.5,791.34 C81.1@531.5,830.33 ; C81.1@531.5,830.33 537.83,823.99 C80.1@570.37,823.99
DPLL_VDDA_BG_LC: C68.1 C69.1 C70.1 L3.2 U11.15 U11.16 | length 292
  L01-TOP w6: v1(604.33,799.21) U11.15@604.33,836.44 ; v1(623.8,783.38) 623.91,783.49 U11.16@623.91,836.33
  L10-BOT w15: C69.1@614.62,843.97 613.27,843.97 610.69,841.39 610.69,840.04 604.33,833.68 v1(604.33,799.21) 604.52,799.02 607.89,799.02 623.53,783.38 v1(623.8,783.38) ; C70.1@623.15,657.48 623.34,657.67 623.34,747.85 C68.1@623.52,748.03 623.66,748.17 v1@623.66,783.24
DPLL_VDDA_FB: C109.1 C110.1 L15.2 U11.47 | length 328.5
  L01-TOP w6: v1(574.8,1157.48) 574.8,1154.77 584.65,1144.93 U11.47@584.65,1108.44
  L10-BOT w15: C110.1@458.98,1332.37 456.88,1330.27 456.88,1289.5 L15.2@454.78,1287.4 456.26,1287.4 486.19,1257.47 486.19,1246.09 v1(574.8,1157.48) 574.8,1157.21 586.07,1145.94 586.07,1120.36 587.43,1119.01 C109.1@591.86,1119.01
DPLL_VDDA_PDCP_XTAL: C84.1 C85.1 L6.2 U11.46 | length 236.3
  L01-TOP w6: U11.46@604.44,1108.55 604.44,1161.39 v1(604.55,1161.5)
  L10-BOT w15: L6.2@592.27,1290.64 592.68,1290.23 592.68,1245.34 C84.1@593.08,1244.94 593.08,1173.23 604.55,1161.77 v1(604.55,1161.5) 604.74,1161.31 604.74,1155.02 633.86,1125.9 C85.1@633.86,1124.54
DPLL_VDDO_Q8: C102.1 C103.1 L13.2 U11.39 | length 240.6
  L01-TOP w6: U11.39@742.13,1110.24 v1(742.13,1147.46)
  L10-BOT w15: C102.1@724.05,1121.12 728.48,1121.12 741.93,1134.57 741.93,1147.27 v1(742.13,1147.46) 741.93,1147.66 741.93,1255.28 C103.1@740.19,1257.03 742.77,1259.61 758.32,1259.61 783.72,1285.02 L13.2@783.72,1286.49
DPLL_VDDO_Q9: C92.1 C93.1 L8.2 U11.35 | length 323.4
  L01-TOP w6: U11.35@809.23,1061.02 v1(846.46,1061.02)
  L10-BOT w15: C92.1@821.36,1039.37 821.36,1043.8 838.39,1060.83 846.27,1060.83 v1(846.46,1061.02) 846.73,1061.02 868.13,1082.43 897.39,1082.43 909.45,1094.49 909.45,1174.46 L8.2@941.69,1206.69 ; L8.2@941.69,1208.17 L8.2@941.69,1206.69 ; C93.1@985.41,1202.03 947.83,1202.03 947.47,1202.38 946,1202.38 L8.2@941.69,1206.69
DPLL_VDDO_Q10: C114.1 C115.1 L16.2 U11.26 | length 182
  L01-TOP w6: U11.26@809.34,883.75 862.18,883.75 v1(862.29,883.64)
  L10-BOT w15: C115.1@827.2,892.05 853.61,892.05 862.02,883.64 v1(862.29,883.64) 862.48,883.45 878.36,883.45 893.21,868.6 C114.1@897.64,868.6 899,867.24 942.3,867.24 L16.2@944.88,864.67
DPLL_VDDO_Q11: C107.1 C108.1 L14.2 U11.22 | length 238.9
  L01-TOP w6: v1(741.91,783.38) 742.02,783.49 U11.22@742.02,836.33
  L10-BOT w15: C108.1@712.6,656.12 714.57,658.09 714.57,690.94 L14.2@716.54,692.91 716.54,758.01 v1(741.91,783.38) 728.35,796.95 C107.1@728.35,824.31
